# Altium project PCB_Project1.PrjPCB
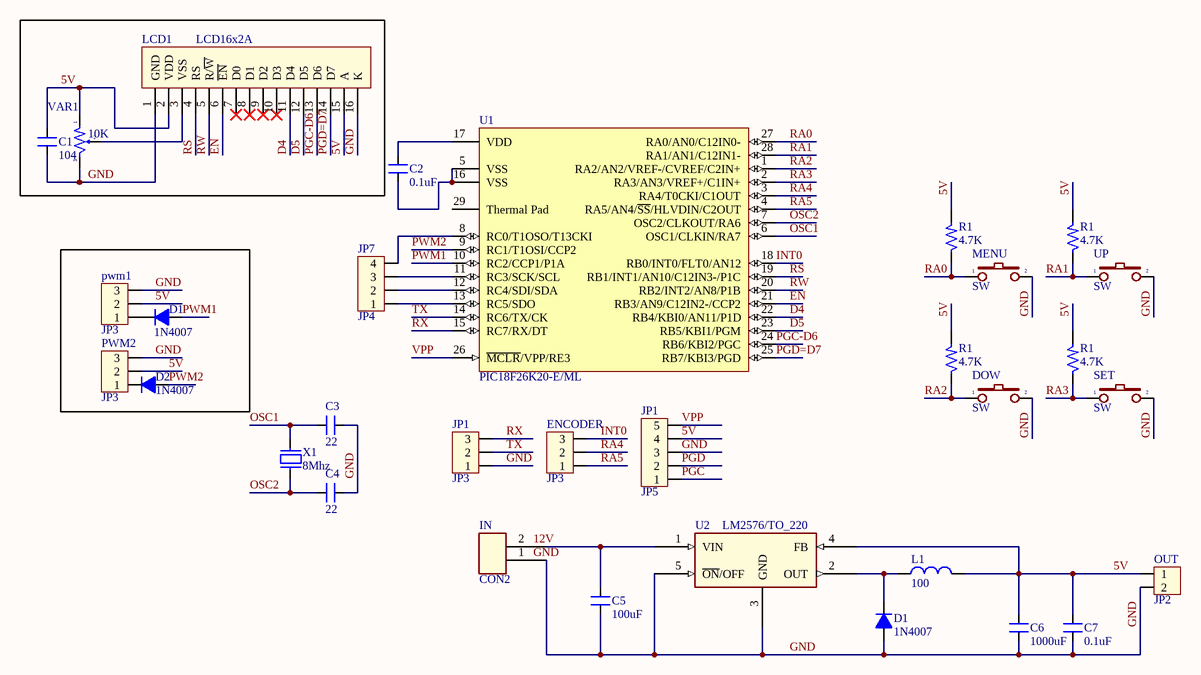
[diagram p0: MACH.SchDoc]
1 sheet, 32 parts. Net scope: global (net labels, ports and power ports of the same name join across sheets).

## Sheet MACH.SchDoc
size A4

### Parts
(Parts that share a designator on the sheet are numbered #1, #2 ... from top to bottom, then left to right.)
C1  104  [SM-0805]
C2  0.1uF  [SM-0805]
C3  22  [SM-0805]
C4  22  [SM-0805]
C5  100uF  [SM-0805]
C6  1000uF  [SM-0805]
C7  0.1uF  [SM-0805]
D1#1  1N4007  [D1A]
D1#2  1N4007  [D1A]
D2  1N4007  [D1A]
DOW  SW  [SW2]
ENCODER  JP3  [CON3]
IN  CON2  [HEADER1x2]
JP1#1  JP3  [CON3]
JP1#2  JP5  [CON5]
JP7  JP4  [CON4]
L1  100  [L/0.4]
LCD1  LCD16x2A  [LCD16X2]
MENU  SW  [SW2]
OUT  JP2  [CON2]
pwm1  JP3  [CON3]
PWM2  JP3  [CON3]
R1#1  4.7K  [SM-1206]
R1#2  4.7K  [SM-1206]
R1#3  4.7K  [SM-1206]
R1#4  4.7K  [SM-1206]
SET  SW  [SW2]
U1  PIC18F26K20-E/ML  [QFN-ML28_N]
U2  LM2576/TO_220  [LM2576_SMD]
UP  SW  [SW2]
VAR1  10K  [VOL-S]
X1  8Mhz  [XT2]

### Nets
5V: C1.2 C6.2 C7.2 JP1#2.4 L1.2 LCD1.2(VDD) LCD1.15(A) OUT.1 pwm1.2 PWM2.2 R1#1.2 R1#2.2 R1#3.2 R1#4.2 U2.4(FB) VAR1.1
D4: LCD1.11(D4) U1.22(RB4/KBI0/AN11/P1D)
D5: LCD1.12(D5) U1.23(RB5/KBI1/PGM)
EN: LCD1.6(~{EN}) U1.21(RB3/AN9/C12IN2-/CCP2)
GND: C1.1 C3.1 C4.1 C5.1 C6.1 C7.1 D1#2.1(A) DOW.2 IN.1 JP1#1.1 JP1#2.3 LCD1.1(GND) LCD1.16(K) MENU.2 OUT.2 pwm1.3 PWM2.3 SET.2 U2.3(GND) U2.5(~{ON}/OFF) UP.2 VAR1.3
INT0: ENCODER.3 U1.18(RB0/INT0/FLT0/AN12)
OSC1: C3.2 U1.6(OSC1/CLKIN/RA7) X1.2
OSC2: C4.2 U1.7(OSC2/CLKOUT/RA6) X1.1
PGC: JP1#2.1
PGC-D6: LCD1.13(D6) U1.24(RB6/KBI2/PGC)
PGD: JP1#2.2
PGD=D7: LCD1.14(D7) U1.25(RB7/KBI3/PGD)
PWM1: D1#1.1(A) U1.10(RC2/CCP1/P1A)
PWM2: D2.1(A) U1.9(RC1/T1OSI/CCP2)
RA0: MENU.1 R1#1.1 U1.27(RA0/AN0/C12IN0-)
RA1: R1#2.1 U1.28(RA1/AN1/C12IN1-) UP.1
RA2: DOW.1 R1#3.1 U1.1(RA2/AN2/VREF-/CVREF/C2IN+)
RA3: R1#4.1 SET.1 U1.2(RA3/AN3/VREF+/C1IN+)
RA4: ENCODER.2 U1.3(RA4/T0CKI/C1OUT)
RA5: ENCODER.1 U1.4(RA5/AN4/~{SS}/HLVDIN/C2OUT)
RS: LCD1.4(RS) U1.19(RB1/INT1/AN10/C12IN3-/P1C)
RW: LCD1.5(R/~{W}) U1.20(RB2/INT2/AN8/P1B)
RX: JP1#1.3 U1.15(RC7/RX/DT)
TX: JP1#1.2 U1.14(RC6/TX/CK)
VPP: JP1#2.5 U1.26(~{MCLR}/VPP/RE3)
NetC2_1: C2.1 U1.5(VSS) U1.16(VSS)
NetC2_2: C2.2 U1.17(VDD)
NetC5_2: C5.2 IN.2 U2.1(VIN)
NetD1#1_2: D1#1.2(K) pwm1.1
NetD1#2_2: D1#2.2(K) L1.1 U2.2(OUT)
NetJP7_1: JP7.1 U1.13(RC5/SDO)
NetJP7_2: JP7.2 U1.12(RC4/SDI/SDA)
NetJP7_3: JP7.3 U1.11(RC3/SCK/SCL)
NetJP7_4: JP7.4 U1.8(RC0/T1OSO/T13CKI)
NetLCD1_3: LCD1.3(VSS) VAR1.2

Not connected (* = marked no-connect by the designer): D2 2(K); LCD1 7(D0)* 8(D1)* 9(D2)* 10(D3)*; PWM2 1; U1 29(Thermal_Pad)

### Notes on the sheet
- Labels drawn without touching a wire or pin: 12V, GND

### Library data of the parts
C1-C7 = CM: Cap SMD; Value: 103
D1#1 D1#2 D2 = D1A: Diode 1A
DOW MENU SET UP = SW2: Switch button 2 pin; Value: SW chip 2 pin
ENCODER JP1#1 pwm1 PWM2 = Con3: Connector 3
JP1#2 = Con5: Connector 5
JP7 = Con4: Connector 4
L1 = L1: Inductor; Value: 150 mH
LCD1 = LCD16x2: LCD dipslay 16 char, 2 line
OUT = Con2: Connector 2
R1#1-R1#4 = R: Resistor 1/4W; Value: R1/4W - 1K
U1 = PIC18F26K20-E/ML: Flash Microcontroller with 10-Bit A/D and nanoWatt Technology, 64K Flash, 28-Pin QFN, Extended Temperature Range
VAR1 = VOL-S: Var Resistor; Value: Volume 50k
X1 = XT2: Crystal For all Crystal 2pin.; Value: 4Mhz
